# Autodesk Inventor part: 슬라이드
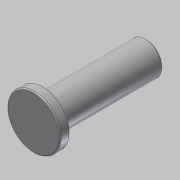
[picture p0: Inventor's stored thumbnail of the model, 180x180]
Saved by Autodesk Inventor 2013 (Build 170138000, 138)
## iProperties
Company: 한국ATC센터
Created: 2015-11
Part Number: 슬라이드
Document SubType Name: Modeling
Designer: mdu
Density: 7.86 g/cm^3
Material: 강철, 연강
Mass: 53.476 g
Surface Area: 25.6477 cm^2
Volume: 6.80356 cm^3
Author: mdu
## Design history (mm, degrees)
sketch "스케치1"
  geometry: L1 (13.5, 41)-(13.5, 74) reference; L2 (13.5, 74)-(26.5, 74) reference; L3 (20, 74)-(20, 29); L4 (20, 74)-(13.5, 74); L5 (13.5, 74)-(13.5, 33); L6 (13.5, 33)-(9.5, 33); L7 (9.5, 33)-(9.5, 29); L8 (20, 73.5)-(13.5, 73.5); L9 (20, 29)-(9.5, 29); 1 further point
  constraints: 16 end point, 4 perpendicular, 3 point on line, 1 collinear, 1 midpoint, 1 parallel, 1 vertical, 2 other
  dimensions: "d0" = 45 distance of L3.start L3.end; "d1" = 21 diameter of L7 L3; "d2" = 4 distance from line of L3.end L6; "d4" = 0.5 distance between parallel lines of L8 L2
revolve "회전1" sketch "스케치1" stored, may be unused: angle "d5" = 90 deg
fillet "모깎기1" dims "d6" = 0.5
chamfer "모따기1" distance "d9" = 0.5; stored, may be unused: second distance "d10" = 2, angle "d11" = 45 deg
node "솔리드1"
node "참조1"
